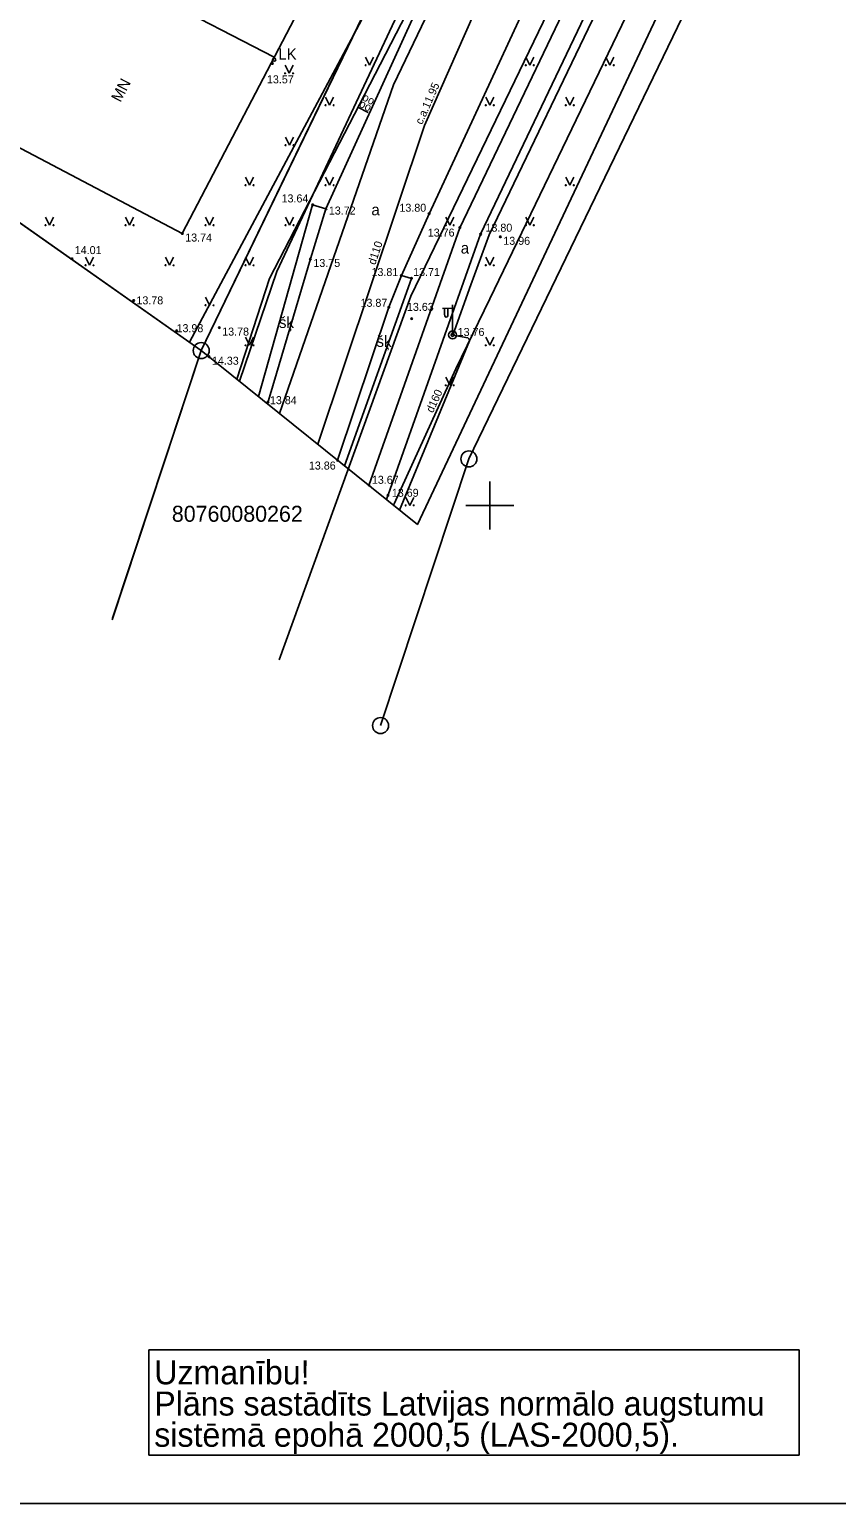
# Model space of a CAD drawing. Extents: x 503904 to 504094, y 304688 to 304960.
# Drawn here: x 503971.2 to 504021.7, y 304687.6 to 304779.7 of the extents above; entities that cross this region are included whole.
import ezdxf

# ---------------------------------------------------------------- set-up
doc = ezdxf.new("R2010")
doc.units = 0
for name, color, linetype in [('APGR_ELEM_####_####_#', 7, 'Continuous'), ('APGR_SARK_####_####_#', 7, 'Continuous'), ('APGS_ELEM_####_####_#', 7, 'Continuous'), ('APGS_VADP_ZSPR_####_#', 7, 'Continuous'), ('BUVE_EKAS_####_####_#', 7, 'Continuous'), ('BUVE_EKAS_RAKS_TKST_#', 7, 'Continuous'), ('CELI_CMAL_####_####_#', 7, 'Continuous'), ('CELI_CSEG_####_TKST_#', 7, 'Continuous'), ('CELI_TAKA_####_####_#', 7, 'Continuous'), ('GAZE_VADP_VSP2_####_#', 7, 'Continuous'), ('GEOD_ELEM_####_####_#', 7, 'Continuous'), ('LKAN_ELEM_####_####_#', 7, 'Continuous'), ('RAMI_PLAN_####_TKST_#', 7, 'Continuous'), ('RAMI_UZMR_####_####_#', 7, 'Continuous'), ('RELJ_AATZ_####_TKST_#', 7, 'Continuous'), ('RELJ_ELEM_####_####_#', 7, 'Continuous'), ('ROBZ_UZMR_####_####_#', 7, 'Continuous'), ('ROBZ_UZMR_####_TKST_#', 7, 'Continuous'), ('SAKK_IZVK_####_TKST_#', 7, 'Continuous'), ('SAKK_KKAN_####_####_#', 7, 'Continuous'), ('SAKT_VADP_KABE_####_#', 7, 'Continuous'), ('SKAN_VADP_SPDK_####_I', 7, 'Continuous'), ('SKAN_VADP_SPDK_TKST_I', 7, 'Continuous'), ('TERT_ELEM_####_####_#', 7, 'Continuous'), ('UDTK_VADP_UDEN_####_#', 7, 'Continuous'), ('UDTK_VADP_UDEN_TKST_#', 7, 'Continuous')]:
    doc.layers.add(name, color=color, linetype=linetype)

msp = doc.modelspace()

# ---------------------------------------------------------------- linework, layer by layer
at = {"layer": 'APGR_ELEM_####_####_#'}
for centre in [(503981.98, 304759.67), (503998.7, 304752.9), (503993.18, 304736.24)]:
    msp.add_circle(centre, 0.5, dxfattribs=at)
at = {"layer": 'APGR_SARK_####_####_#'}
for p, q in [((504030.463, 304860.121), (503981.982, 304759.672)), ((504032.794, 304823.54), (503998.701, 304752.902)), ((503981.982, 304759.672), (503976.411, 304742.854)), ((503998.701, 304752.902), (503993.181, 304736.236))]:
    msp.add_line(p, q, dxfattribs=at)
at = {"layer": 'APGS_ELEM_####_####_#'}
for p, q in [((503997.68, 304762.314), (503997.045, 304762.309)), ((503997.18, 304762.31), (503997.18, 304761.918)), ((503997.39, 304762.312), (503997.39, 304761.918)), ((503997.68, 304760.647), (503997.68, 304762.53))]:
    msp.add_line(p, q, dxfattribs=at)
for radius in [0.25, 0.09]:
    msp.add_circle((503997.68, 304760.647), radius, dxfattribs=at)
msp.add_ellipse((503997.285, 304761.918), major_axis=(0, 0.151), ratio=0.695971, start_param=1.570796, end_param=4.712389, dxfattribs=at)
at = {"layer": 'APGS_VADP_ZSPR_####_#'}
for points in [[(503997.69, 304760.643), (503998.828, 304763.774), (503999.966, 304766.905), (504007.201, 304781.962), (504014.402, 304796.949)], [(503994.367, 304749.708), (503998.727, 304760.287), (503998.71, 304760.385), (503998.633, 304760.466), (503997.69, 304760.643)]]:
    msp.add_lwpolyline(points, dxfattribs=at)
at = {"layer": 'BUVE_EKAS_####_####_#'}
for p, q in [((503980.794, 304766.985), (504014.326, 304831.324)), ((503986.542, 304778.014), (503972.696, 304785.199)), ((503966.985, 304774.25), (503980.794, 304766.985))]:
    msp.add_line(p, q, dxfattribs=at)
at = {"layer": 'CELI_CMAL_####_####_#'}
for points in [[(503992.452, 304751.249), (503998.132, 304767.348), (504007.65, 304787.237), (504015.889, 304804.514), (504022.724, 304818.878), (504029.221, 304830.725)], [(504030.694, 304830.598), (504023.914, 304818.199), (504017.078, 304803.923), (504008.828, 304786.666), (503999.434, 304766.943), (503993.551, 304750.365)], [(503990.5, 304752.82), (503993.697, 304762.375), (503994.484, 304764.359), (503996.214, 304768.221), (504005.642, 304788.589), (504013.779, 304805.451), (504020.778, 304819.846), (504026.069, 304828.977)], [(504013.046, 304817.755), (504007.946, 304807.438), (504002.84, 304796.556), (503998.081, 304787.166), (503995.164, 304780.353), (503989.767, 304768.519), (503988.799, 304765.396), (503986.11, 304756.351)]]:
    msp.add_lwpolyline(points, dxfattribs=at)
at = {"layer": 'CELI_TAKA_####_####_#'}
for points in [[(503985.546, 304756.805), (503988.937, 304768.776), (503989.767, 304768.519)], [(503990.929, 304752.474), (503995.111, 304764.182), (503994.484, 304764.359)]]:
    msp.add_lwpolyline(points, dxfattribs=at)
at = {"layer": 'GAZE_VADP_VSP2_####_#'}
msp.add_lwpolyline([(504042.754, 304870.726), (504040.842, 304866.35), (504038.93, 304861.973), (504035.12, 304854.33), (504031.31, 304846.687), (504029.002, 304842.057), (504026.694, 304837.426), (504024.595, 304833.216), (504022.496, 304829.005), (504019.148, 304822.29), (504017.375, 304818.733), (504013.61, 304817.132), (504006.805, 304802.964), (504000, 304788.796), (503996.994, 304782.538), (503993.988, 304776.279), (503986.861, 304755.747)], dxfattribs=at)
at = {"layer": 'GEOD_ELEM_####_####_#'}
for p, q in [((504000, 304751.5), (504000, 304750)), ((503998.5, 304750), (504000, 304750)), ((504000, 304750), (504000, 304748.5)), ((504000, 304750), (504001.5, 304750))]:
    msp.add_line(p, q, dxfattribs=at)
at = {"layer": 'LKAN_ELEM_####_####_#'}
msp.add_circle((503986.531, 304777.848), 0.1, dxfattribs=at)
at = {"layer": 'RAMI_PLAN_####_TKST_#'}
for p, q in [((503978.71, 304697.244), (504019.33, 304697.244)), ((503978.71, 304690.65), (503978.71, 304697.244)), ((504019.33, 304697.244), (504019.33, 304690.65)), ((504019.33, 304690.65), (503978.71, 304690.65))]:
    msp.add_line(p, q, dxfattribs=at)
msp.add_lwpolyline([(503904.204, 304823.741), (504093.703, 304823.741), (504093.703, 304687.633), (503904.204, 304687.633)], close=True, dxfattribs=at)
at = {"layer": 'RAMI_UZMR_####_####_#'}
msp.add_lwpolyline([(503923.253, 304801.015), (503981.982, 304759.672), (503995.48, 304748.813), (504027.75, 304817.255), (504060.02, 304885.696), (504048.875, 304885.773), (504036.803, 304888.853), (503994.536, 304908.303), (503981.123, 304894.75), (503978.518, 304892.436), (503950.886, 304846.726), (503923.253, 304801.015)], dxfattribs=at)
at = {"layer": 'RELJ_ELEM_####_####_#'}
for centre in [(503986.418, 304777.609), (503988.937, 304768.776), (503989.767, 304768.519), (503996.214, 304768.221), (503980.794, 304766.985), (503998.132, 304767.348), (503999.434, 304766.943), (504000.664, 304766.78), (503973.904, 304765.406), (503988.799, 304765.396), (503994.484, 304764.359), (503995.111, 304764.182), (503977.76, 304762.797), (503993.697, 304762.375), (503995.129, 304761.666), (503980.438, 304760.909), (503983.103, 304761.108), (503982.461, 304759.287), (503986.147, 304756.463), (503990.501, 304752.814), (503992.462, 304751.277), (503993.645, 304750.63)]:
    msp.add_circle(centre, 0.05, dxfattribs=at)
at = {"layer": 'ROBZ_UZMR_####_####_#'}
msp.add_lwpolyline([(503923.29, 304801.044), (503978.518, 304892.436), (503981.123, 304894.75), (504030.463, 304860.121), (503981.982, 304759.672)], close=True, dxfattribs=at)
for points in [[(503976.684, 304743.679), (503981.982, 304759.672), (504030.463, 304860.121), (504048.85, 304847.4), (504035.67, 304821.93), (504026.069, 304827.305), (503995.067, 304763.071), (503986.854, 304740.353)], [(503918.172, 304804.652), (503923.29, 304801.044), (503981.982, 304759.672), (503976.441, 304742.944)]]:
    msp.add_lwpolyline(points, dxfattribs=at)
at = {"layer": 'SAKK_IZVK_####_TKST_#'}
msp.add_line((503991.77, 304774.883), (503992.409, 304774.553), dxfattribs=at)
at = {"layer": 'SAKK_KKAN_####_####_#'}
msp.add_lwpolyline([(504039.007, 304870.064), (504036.678, 304863.872), (504034.349, 304857.68), (504031.408, 304852.312), (504030.269, 304850.237), (504027.088, 304844.191), (504022.232, 304834.693), (504020.138, 304830.591), (504009.306, 304809.848), (504000, 304790.89), (503998.089, 304787.127), (503992.169, 304775.655), (503986.248, 304764.183), (503984.196, 304757.891)], dxfattribs=at)
at = {"layer": 'SAKT_VADP_KABE_####_#'}
msp.add_lwpolyline([(503984.36, 304757.759), (503986.696, 304764.614), (504000.633, 304794.323), (504014.571, 304824.033), (504017.941, 304829.488), (504018.377, 304830.312), (504025.72, 304844.17), (504033.498, 304858.852), (504046.129, 304856.235)], dxfattribs=at)
at = {"layer": 'SKAN_VADP_SPDK_####_I'}
msp.add_lwpolyline([(503989.264, 304753.814), (503995.932, 304773.743), (504000, 304782.989), (504006.638, 304798.076), (504017.345, 304822.408), (504018.739, 304825.349), (504022.372, 304833.011), (504023.783, 304835.985)], dxfattribs=at)
at = {"layer": 'TERT_ELEM_####_####_#'}
for p, q in [((503992.25, 304778), (503992.5, 304777.5)), ((503992.5, 304777.5), (503992.75, 304778)), ((504002.25, 304778), (504002.5, 304777.5)), ((504002.5, 304777.5), (504002.75, 304778)), ((504007.25, 304778), (504007.5, 304777.5)), ((504007.5, 304777.5), (504007.75, 304778)), ((503987.215, 304777.495), (503987.465, 304776.995)), ((503987.465, 304776.995), (503987.715, 304777.495)), ((503989.75, 304775.5), (503990, 304775)), ((503990, 304775), (503990.25, 304775.5)), ((503999.75, 304775.5), (504000, 304775)), ((504000, 304775), (504000.25, 304775.5)), ((504004.75, 304775.5), (504005, 304775)), ((504005, 304775), (504005.25, 304775.5)), ((503987.25, 304773), (503987.5, 304772.5)), ((503987.5, 304772.5), (503987.75, 304773)), ((503984.75, 304770.5), (503985, 304770)), ((503985, 304770), (503985.25, 304770.5)), ((503989.75, 304770.5), (503990, 304770)), ((503990, 304770), (503990.25, 304770.5)), ((504004.75, 304770.5), (504005, 304770)), ((504005, 304770), (504005.25, 304770.5)), ((503972.25, 304768), (503972.5, 304767.5)), ((503972.5, 304767.5), (503972.75, 304768)), ((503977.25, 304768), (503977.5, 304767.5)), ((503977.5, 304767.5), (503977.75, 304768)), ((503982.25, 304768), (503982.5, 304767.5)), ((503982.5, 304767.5), (503982.75, 304768)), ((503987.25, 304768), (503987.5, 304767.5)), ((503987.5, 304767.5), (503987.75, 304768)), ((503997.25, 304768), (503997.5, 304767.5)), ((503997.5, 304767.5), (503997.75, 304768)), ((504002.25, 304768), (504002.5, 304767.5)), ((504002.5, 304767.5), (504002.75, 304768)), ((503974.75, 304765.5), (503975, 304765)), ((503975, 304765), (503975.25, 304765.5)), ((503979.75, 304765.5), (503980, 304765)), ((503980, 304765), (503980.25, 304765.5)), ((503984.75, 304765.5), (503985, 304765)), ((503985, 304765), (503985.25, 304765.5)), ((503999.75, 304765.5), (504000, 304765)), ((504000, 304765), (504000.25, 304765.5)), ((503982.25, 304763), (503982.5, 304762.5)), ((503982.5, 304762.5), (503982.75, 304763)), ((503984.75, 304760.5), (503985, 304760)), ((503985, 304760), (503985.25, 304760.5)), ((503999.75, 304760.5), (504000, 304760)), ((504000, 304760), (504000.25, 304760.5)), ((503997.25, 304758), (503997.5, 304757.5)), ((503997.5, 304757.5), (503997.75, 304758)), ((503994.75, 304750.5), (503995, 304750)), ((503995, 304750), (503995.25, 304750.5))]:
    msp.add_line(p, q, dxfattribs=at)
for centre, radius in [((503987.215, 304776.994), 0.028), ((503987.715, 304776.994), 0.0263), ((503992.25, 304777.5), 0.028), ((503992.75, 304777.5), 0.0263), ((504002.25, 304777.5), 0.028), ((504002.75, 304777.5), 0.0263), ((504007.25, 304777.5), 0.028), ((504007.75, 304777.5), 0.0263), ((503989.75, 304775), 0.028), ((503990.25, 304775), 0.0263), ((503999.75, 304775), 0.028), ((504000.25, 304775), 0.0263), ((504004.75, 304775), 0.028), ((504005.25, 304775), 0.0263), ((503987.25, 304772.5), 0.028), ((503987.75, 304772.5), 0.0263), ((503984.75, 304770), 0.028), ((503985.25, 304770), 0.0263), ((503989.75, 304770), 0.028), ((503990.25, 304770), 0.0263), ((504004.75, 304770), 0.028), ((504005.25, 304770), 0.0263), ((503972.25, 304767.5), 0.028), ((503972.75, 304767.5), 0.0263), ((503977.25, 304767.5), 0.028), ((503977.75, 304767.5), 0.0263), ((503982.25, 304767.5), 0.028), ((503982.75, 304767.5), 0.0263), ((503987.25, 304767.5), 0.028), ((503987.75, 304767.5), 0.0263), ((503997.25, 304767.5), 0.028), ((503997.75, 304767.5), 0.0263), ((504002.25, 304767.5), 0.028), ((504002.75, 304767.5), 0.0263), ((503974.75, 304765), 0.028), ((503975.25, 304765), 0.0263), ((503979.75, 304765), 0.028), ((503980.25, 304765), 0.0263), ((503984.75, 304765), 0.028), ((503985.25, 304765), 0.0263), ((503999.75, 304765), 0.028), ((504000.25, 304765), 0.0263), ((503982.25, 304762.5), 0.028), ((503982.75, 304762.5), 0.0263), ((503984.75, 304760), 0.028), ((503985.25, 304760), 0.0263), ((503999.75, 304760), 0.028), ((504000.25, 304760), 0.0263), ((503997.25, 304757.5), 0.028), ((503997.75, 304757.5), 0.0263), ((503994.75, 304750), 0.028), ((503995.25, 304750), 0.0263)]:
    msp.add_circle(centre, radius, dxfattribs=at)
at = {"layer": 'UDTK_VADP_UDEN_####_#'}
for points in [[(504052.599, 304884.688), (504054.563, 304874.709), (504047.684, 304860.837), (504037.414, 304840.144), (504031.385, 304827.996), (504014.788, 304793.579), (504000, 304762.914), (503998.944, 304760.723), (503997.887, 304758.532), (503994.035, 304750.096), (503993.994, 304750.008)], [(504035.876, 304862.497), (503981.246, 304760.191)]]:
    msp.add_lwpolyline(points, dxfattribs=at)

# ---------------------------------------------------------------- texts
at = {"layer": 'BUVE_EKAS_RAKS_TKST_#'}
msp.add_text('MN', height=0.7, rotation=62.47252, dxfattribs=at).set_placement((503976.931, 304775.142))
at = {"layer": 'CELI_CSEG_####_TKST_#'}
for s, p in [('a', (503992.61, 304768.123)), ('a', (503998.191, 304765.733)), ('šķ', (503986.834, 304761.083)), ('šķ', (503992.926, 304759.902))]:
    msp.add_text(s, height=0.7, dxfattribs=at).set_placement(p)
at = {"layer": 'LKAN_ELEM_####_####_#'}
msp.add_text(' LK', height=0.7, dxfattribs=at).set_placement((503986.531, 304777.848))
at = {"layer": 'RAMI_PLAN_####_TKST_#'}
for s, p in [('Uzmanību!', (503979.045, 304695.079)), ('Plāns sastādīts Latvijas normālo augstumu', (503979.045, 304693.129)), ('sistēmā epohā 2000,5 (LAS-2000,5).', (503979.045, 304691.179))]:
    msp.add_text(s, height=1.5, rotation=360, dxfattribs=at).set_placement(p)
at = {"layer": 'RELJ_AATZ_####_TKST_#'}
for s, p in [(' 13.57', (503985.897, 304776.369)), (' 13.64', (503986.811, 304768.929)), (' 13.72', (503989.763, 304768.171)), (' 13.80', (503994.174, 304768.347)), (' 13.74', (503980.794, 304766.485)), (' 13.76', (503995.944, 304766.795)), (' 13.80', (503999.551, 304767.1)), (' 13.96', (504000.664, 304766.28)), (' 14.01', (503973.893, 304765.7)), (' 13.75', (503988.799, 304764.896)), (' 13.81', (503992.429, 304764.329)), (' 13.71', (503995.033, 304764.331)), (' 13.78', (503977.744, 304762.559)), (' 13.87', (503991.743, 304762.407)), (' 13.63', (503994.644, 304762.151)), (' 13.98', (503980.25, 304760.821)), (' 13.78', (503983.103, 304760.608)), (' 13.76', (503997.813, 304760.585)), (' 14.33', (503982.461, 304758.787)), (' 13.84', (503986.084, 304756.322)), (' 13.86', (503988.518, 304752.238)), (' 13.67', (503992.454, 304751.348)), (' 13.69', (503993.7, 304750.537))]:
    msp.add_text(s, height=0.5, dxfattribs=at).set_placement(p)
at = {"layer": 'ROBZ_UZMR_####_TKST_#'}
msp.add_text('80760080262', height=1, dxfattribs=at).set_placement((503980.142, 304748.975))
at = {"layer": 'SAKK_IZVK_####_TKST_#'}
for p in [(503991.796, 304774.936), (503991.997, 304775.339)]:
    msp.add_text('oo', height=0.5, rotation=332.70253, dxfattribs=at).set_placement(p)
at = {"layer": 'SKAN_VADP_SPDK_TKST_I'}
for s, rotation, p in [('c.a.11.95', 66.25023, (503995.774, 304773.757)), ('d110', 71.50145, (503992.847, 304764.995))]:
    msp.add_text(s, height=0.5, rotation=rotation, dxfattribs=at).set_placement(p)
at = {"layer": 'UDTK_VADP_UDEN_TKST_#'}
msp.add_text('d160', height=0.5, rotation=65.45502, dxfattribs=at).set_placement((503996.449, 304755.745))

doc.saveas('drawing.dxf')
